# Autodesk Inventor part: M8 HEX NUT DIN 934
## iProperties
Created: 2006-02
Part Number: M8 HEX NUT DIN 934
Material: Steel, Mild
Description: Hex Nut
Document SubType Name: Modeling
Standard: DIN 934
Designer: Andy Moles
Standards Organization: DIN
Language: en-US
Size Designation: M8
Categories: <MemberInstance><Categories><Category DisplayName="Fasteners" InternalName="e4da775c-781d-43d5-af7c-5136215cf5a6" Mnemonic="FSTN"><Category DisplayName="Nuts" I
Mass: 5.38751 g
Surface Area: 5.92403 cm^2
Volume: 0.685433 cm^3
Density: 7.86 g/cm^3
Author: Andy Moles
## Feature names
1. Body [Extrusion]
2. Chamfer1 [Revolution]
3. Thread [Hole]
4. Chamfer2
5. Chamfer3
